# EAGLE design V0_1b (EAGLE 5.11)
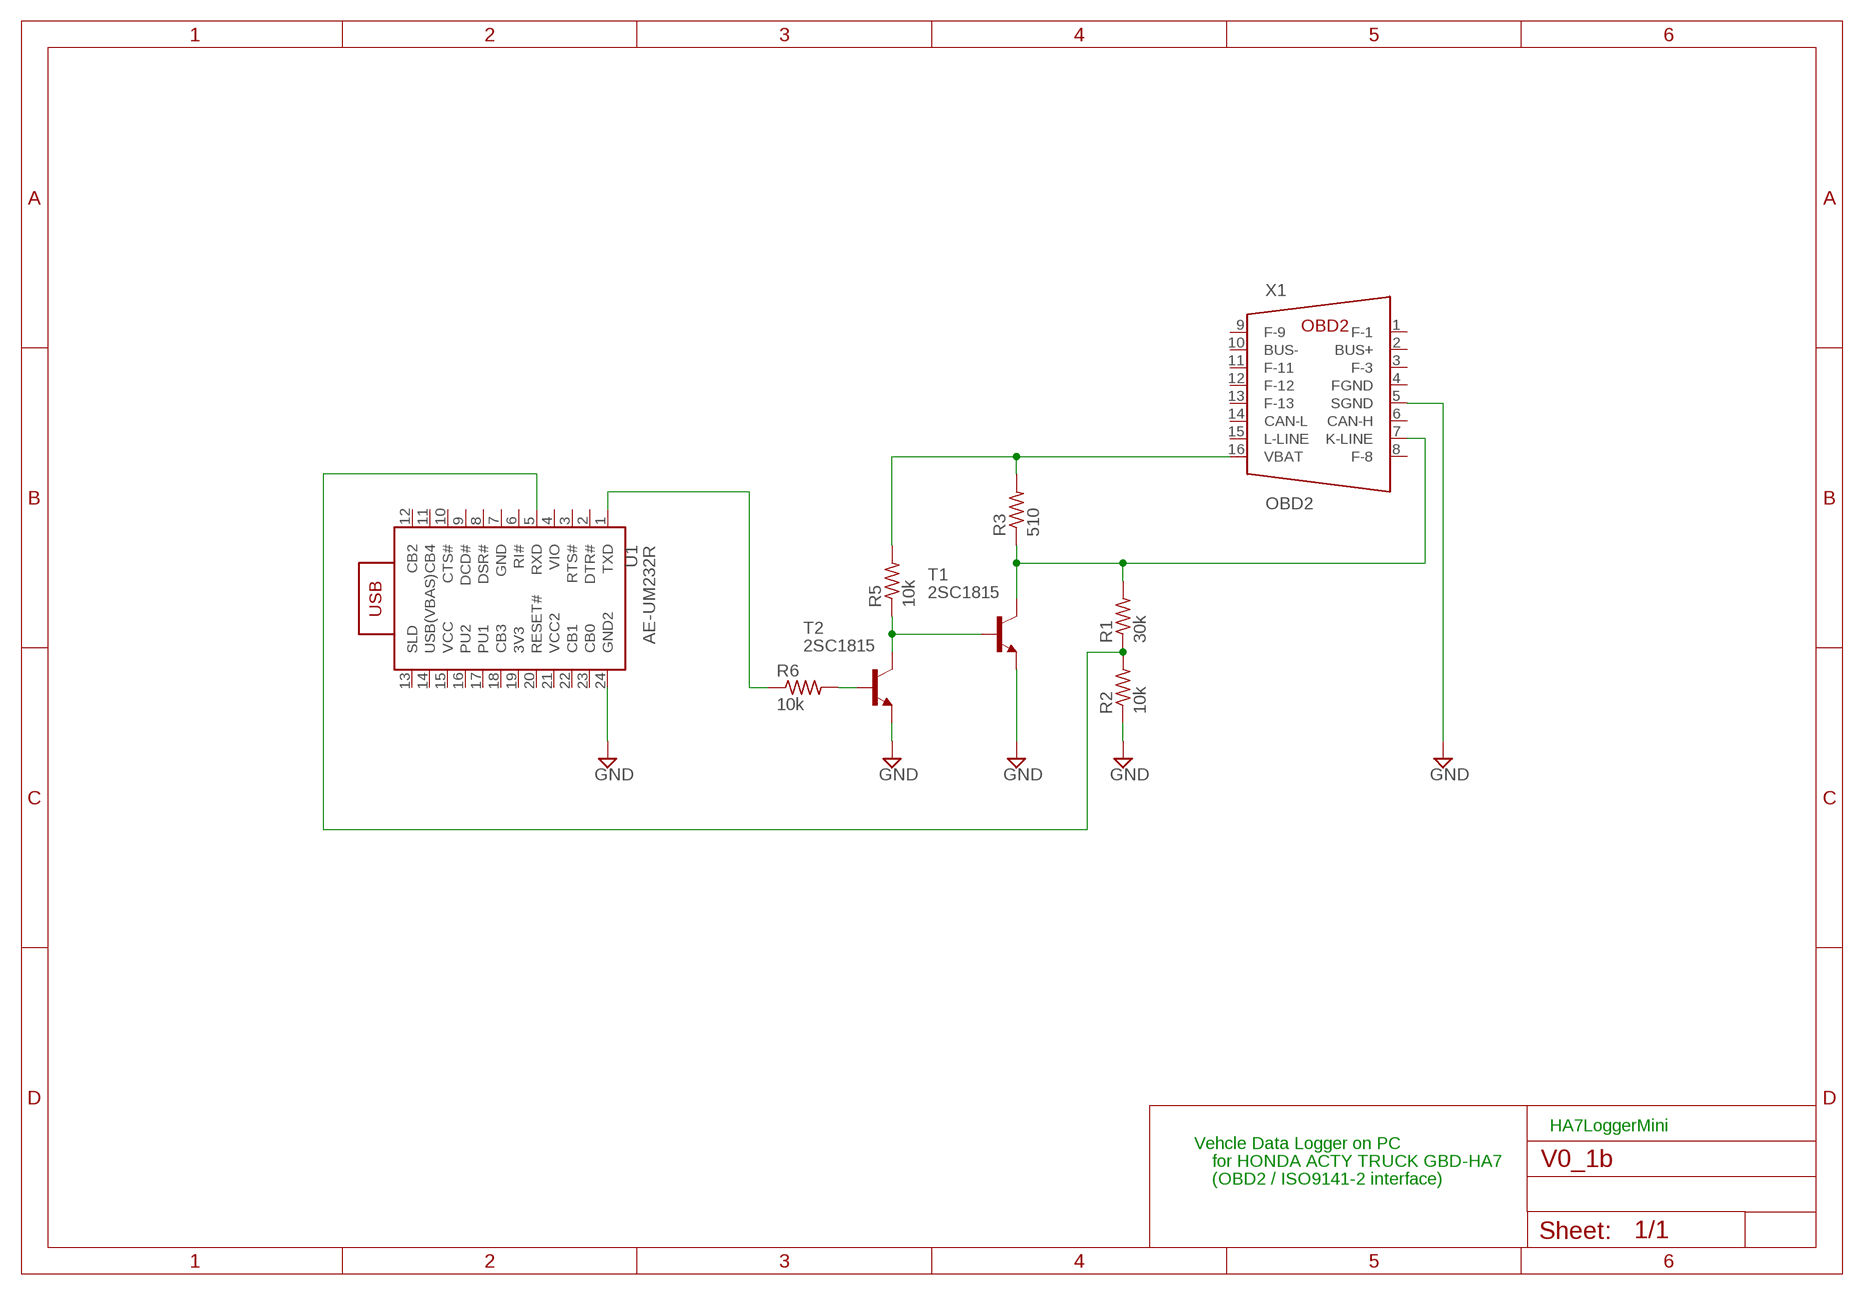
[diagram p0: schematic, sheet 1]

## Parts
R1  30k  R-US_0204/5  [0204/5]
R2  10k  R-US_0204/5  [0204/5]
R3  510  R-US_0204/5  [0204/5]
R5  10k  R-US_0204/5  [0204/5]
R6  10k  R-US_0204/5  [0204/5]
T1  2SC1815  BF420-NPN-TO92-BCE  [TO92-BCE]
T2  2SC1815  BF420-NPN-TO92-BCE  [TO92-BCE]
U1  AE-UM232R  [DIL24-6]
X1  OBD2  [2X08]

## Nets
GND: R2.1 T1.E T2.E U1.24(GND2) X1.5(SGND)
N$1: R1.1 R2.2 U1.5(RXD)
N$3: R6.2 T2.B
N$4: R5.1 T1.B T2.C
N$5: R1.2 R3.1 T1.C X1.7(K-LINE)
N$7: R6.1 U1.1(TXD)
N$8: R3.2 R5.2 X1.16(VBAT)
Unconnected: U1.2(DTR#) U1.3(RTS#) U1.4(VIO) U1.6(RI#) U1.8(DSR#) U1.9(DCD#) U1.10(CTS#) U1.11(CB4) U1.12(CB2) U1.13(SLD) U1.14(USB(VBAS)) U1.16(PU2) U1.17(PU1) U1.18(CB3) U1.20(RESET#) U1.22(CB1) U1.23(CB0) X1.1(F-1) X1.2(BUS+) X1.3(F-3) X1.6(CAN-H) X1.8(F-8) X1.9(F-9) X1.10(BUS-) X1.11(F-11) X1.12(F-12) X1.13(F-13) X1.14(CAN-L) X1.15(L-LINE)

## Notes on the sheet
- HA7LoggerMini
- Vehcle Data Logger on PC
- for HONDA ACTY TRUCK GBD-HA7
- (OBD2 / ISO9141-2 interface)

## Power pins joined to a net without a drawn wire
3V3: U1.19(3V3)
FGND: X1.4(FGND)
GND: U1.7(GND)
VCC: U1.15(VCC)
VCC2: U1.21(VCC2)

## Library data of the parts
R1-R3 R5 R6 = rcl:R-US_: RESISTOR, American symbol
T1 T2 = transistor:*-NPN-: NPN Transistror BF959 corrected 2008.03.06
U1 = TOG:AE-UM232R: Akizuki electric trade. USB-Serial converter module. FTDI FT232RL Chip
X1 = TOG:OBD2: OBD2 Connecter

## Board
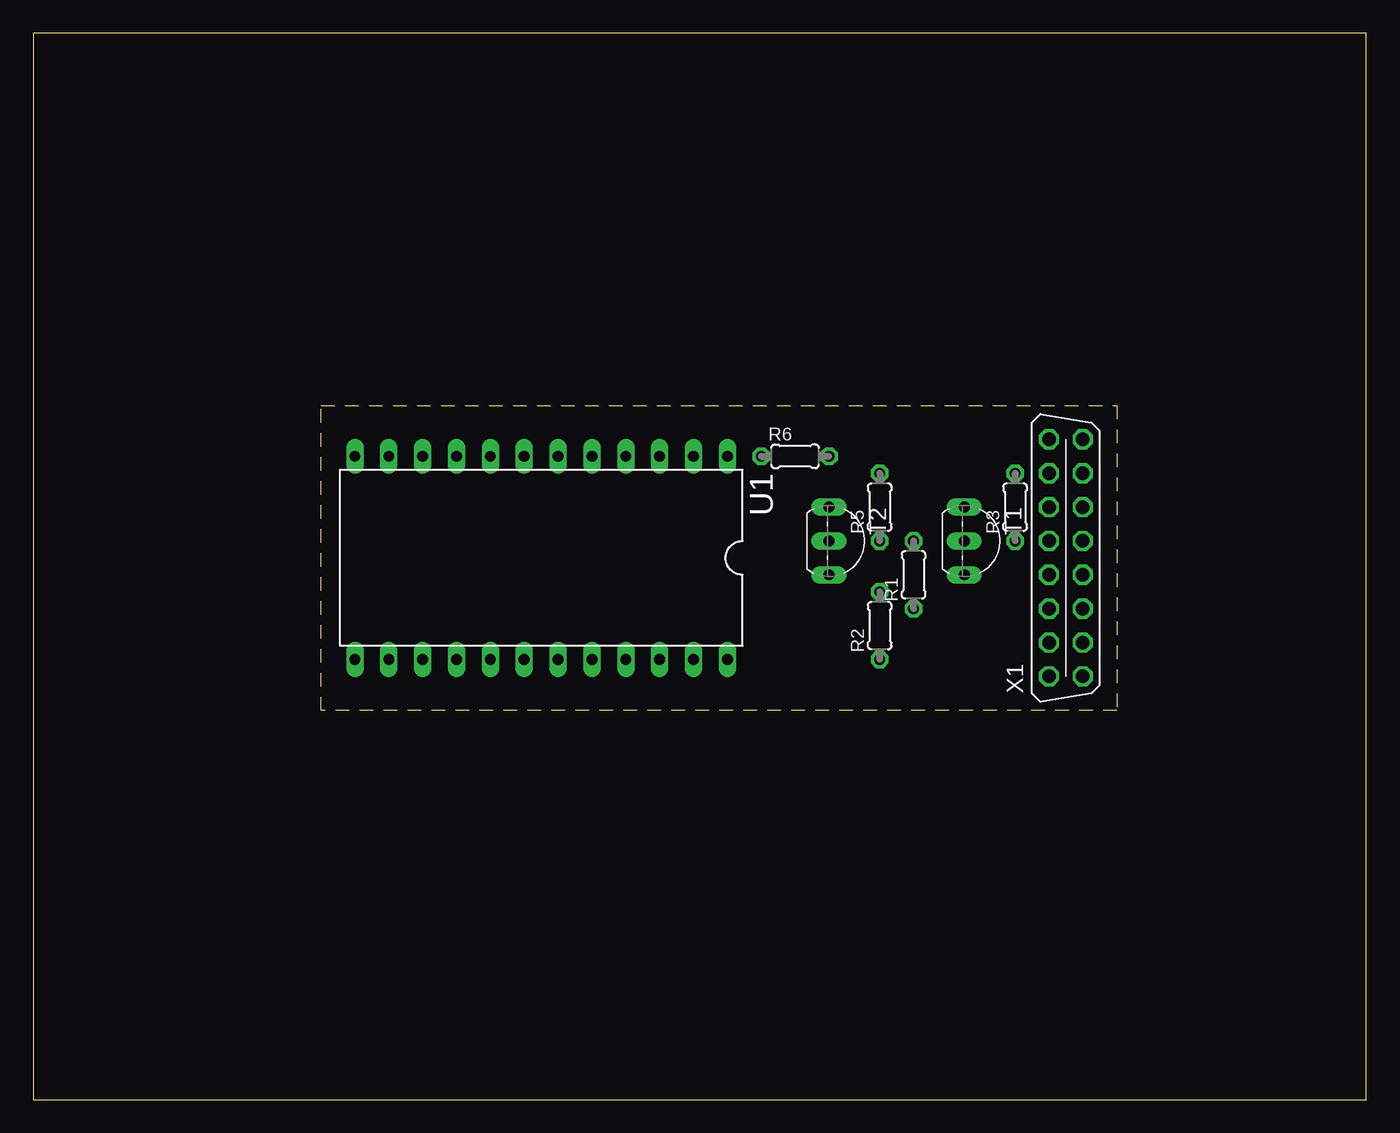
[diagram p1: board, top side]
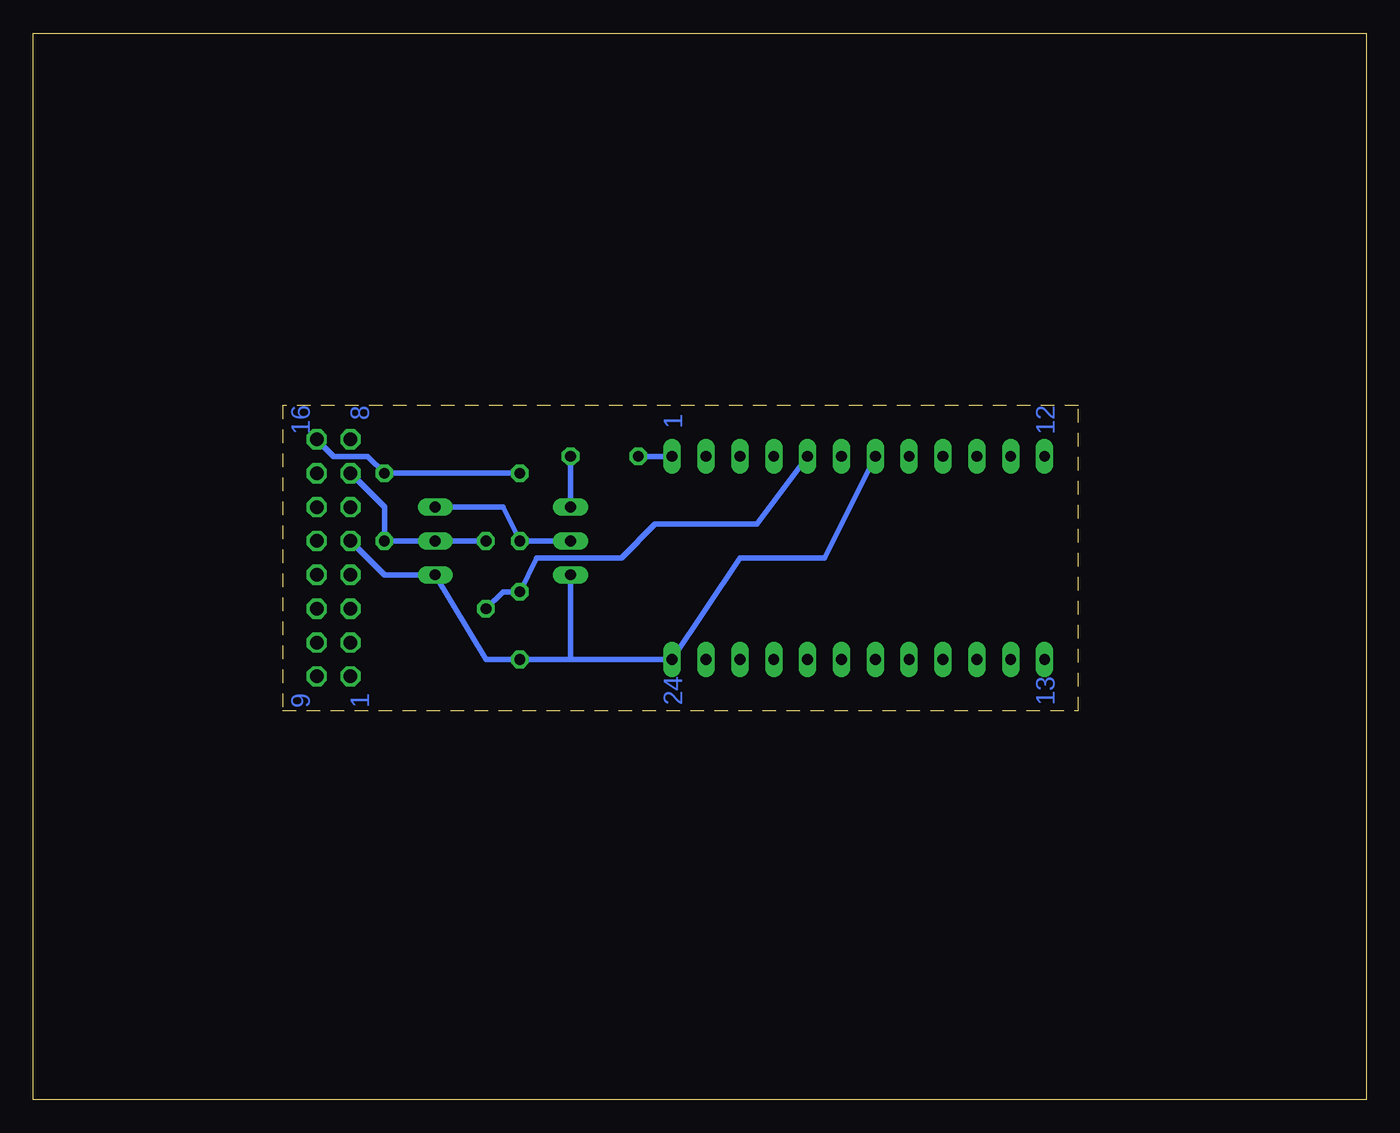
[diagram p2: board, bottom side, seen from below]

Size 100 x 80 mm. Coordinates in mm from the lower left corner, seen from the top.
Outline: 0,0 100,0 100,80 0,80 0,0
Outline: 21.59,52.07 81.28,52.07 81.28,29.21 21.59,29.21 21.59,52.07
Copper layers (1*16): Top 0.035mm / dielectric 1.5mm / Bottom 0.035mm
Design rules "default": minimum track width 10mil, minimum drill 24mil, track to track 8mil, track to pad 8mil, pad to pad 8mil, via to via 8mil, smd to smd 8mil, copper to edge 40mil, drill to drill 8mil, minimum pad ring 10mil, minimum via ring 8mil, stop-mask expansion 4mil, vias tented up to drill 0mil, thermal gap 10mil

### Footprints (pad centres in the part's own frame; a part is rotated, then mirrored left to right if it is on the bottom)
0204/5 = drill 0.813 octagon: 1 -2.54,0; 2 2.54,0
TO92-BCE = drill 0.813 long: B -2.54,0; C 0,0; E 2.54,0
DIL24-6 = drill 0.813 long: 1 -13.97,-7.62; 2 -11.43,-7.62; 3 -8.89,-7.62; 4 -6.35,-7.62; 5 -3.81,-7.62; 6 -1.27,-7.62; 7 1.27,-7.62; 8 3.81,-7.62; 9 6.35,-7.62; 10 8.89,-7.62; 11 11.43,-7.62; 12 13.97,-7.62; 13 13.97,7.62; 14 11.43,7.62; 15 8.89,7.62; 16 6.35,7.62; 17 3.81,7.62; 18 1.27,7.62; 19 -1.27,7.62; 20 -3.81,7.62; 21 -6.35,7.62; 22 -8.89,7.62; 23 -11.43,7.62; 24 -13.97,7.62
2X08 = drill 1.016 octagon: 1 -8.89,1.27; 2 -6.35,1.27; 3 -1.27,1.27; 4 -3.81,1.27; 5 1.27,1.27; 6 3.81,1.27; 7 6.35,1.27; 8 8.89,1.27; 9 -8.89,-1.27; 10 -6.35,-1.27; 11 -3.81,-1.27; 12 -1.27,-1.27; 13 1.27,-1.27; 14 3.81,-1.27; 15 6.35,-1.27; 16 8.89,-1.27

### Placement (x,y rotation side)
R1  66.04,39.37 90 top
R2  63.5,35.56 90 top
R3  73.66,44.45 90 top
R5  63.5,44.45 90 top
R6  57.15,48.26 0 top
T1  69.85,41.91 270 top
T2  59.69,41.91 270 top
U1  38.1,40.64 180 top
X1  77.47,40.64 90 top

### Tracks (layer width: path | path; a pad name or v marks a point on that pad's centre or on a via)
GND
  Bottom 0.406: 59.69,33.02 R2.1 66.04,33.02 T1.E 73.66,39.37 X1.5 | 59.69,33.02 T2.E | U1.7 40.64,40.64 46.99,40.64 U1.24 59.69,33.02
N$1
  Bottom 0.406: R1.1 64.77,38.1 R2.2 62.23,40.64 55.88,40.64 53.34,43.18 45.72,43.18 U1.5
N$3
  Bottom 0.406: T2.B R6.2
N$4
  Bottom 0.406: T1.B 64.77,44.45 R5.1 T2.C
N$5
  Bottom 0.406: R1.2 T1.C R3.1 73.66,44.45 X1.7
N$7
  Bottom 0.406: U1.1 R6.1
N$8
  Bottom 0.406: R5.2 R3.2 74.93,48.26 77.47,48.26 X1.16

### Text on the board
Bottom: 12 | 8 | 16 | 1 | 13 | 24 | 1 | 9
